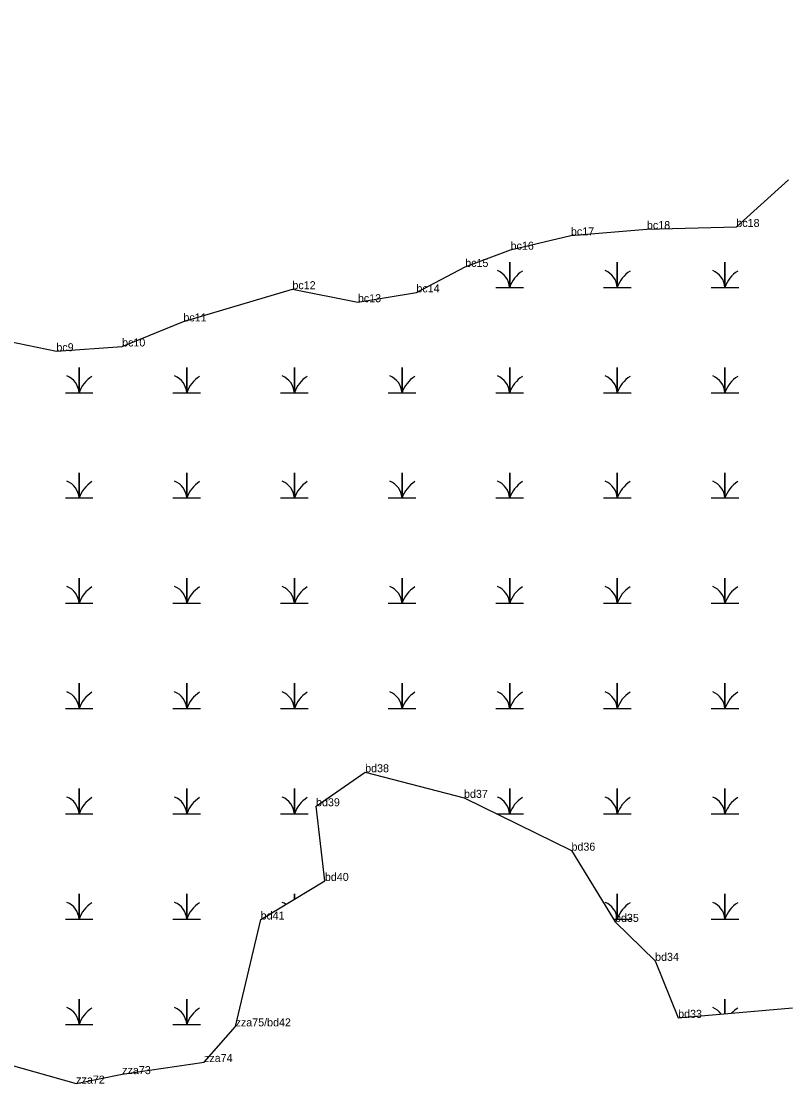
# Model space of a CAD drawing. Extents: x 2072529 to 2268796, y 436423 to 470406.
# Drawn here: x 2214824 to 2215304, y 439449 to 440113 of the extents above; entities that cross this region are included whole.
import ezdxf

# ---------------------------------------------------------------- set-up
doc = ezdxf.new("R2010")
doc.units = 0
for name, color, linetype in [('Exist Environmental Wetland Boundary', 7, 'Continuous'), ('Exist Environmental Wetland Boundary Cogo Comment', 7, 'Continuous'), ('Exist Hydro Swamp or Marsh', 7, 'Continuous'), ('Old_Level_20', 7, 'Continuous')]:
    doc.layers.add(name, color=color, linetype=linetype)

msp = doc.modelspace()

# ---------------------------------------------------------------- linework, layer by layer
at = {"layer": 'Exist Environmental Wetland Boundary'}
for points in [[(2214667.01, 440113.14), (2214653.54, 440085.32), (2214640.79, 440044.09), (2214670.86, 440006.51), (2214705.05, 439986.15), (2214750.6, 439980.47), (2214768.48, 439956.79), (2214803.77, 439915.77), (2214846.21, 439906.91), (2214887.26, 439909.88), (2214925.55, 439925.54), (2214993.67, 439945.68), (2215034.57, 439937.55), (2215071.14, 439943.7), (2215101.61, 439959.58), (2215129.98, 439970.34), (2215167.67, 439979.26), (2215215.16, 439983.25), (2215271.02, 439984.57), (2215303.54, 440013.99)], [(2214798.67, 439466.07), (2214858.58, 439449.17), (2214887.32, 439455.11), (2214938.43, 439462.67), (2214958.15, 439484.96), (2214973.84, 439551.74), (2215013.96, 439575.86), (2215008.43, 439622.52), (2215039.12, 439643.79), (2215100.88, 439627.77), (2215168.02, 439594.78), (2215195.22, 439550.26), (2215220.25, 439525.91), (2215234.65, 439490.29), (2215306.13, 439496.6)]]:
    msp.add_lwpolyline(points, dxfattribs=at)
at = {"layer": 'Exist Hydro Swamp or Marsh'}
for points in [[(2215120.8, 439946.79), (2215129.4, 439946.79), (2215129.4, 439962.57), (2215129.4, 439946.79), (2215138, 439946.79)], [(2215188.05, 439946.79), (2215196.65, 439946.79), (2215196.65, 439962.57), (2215196.65, 439946.79), (2215205.25, 439946.79)], [(2215255.3, 439946.79), (2215263.9, 439946.79), (2215263.9, 439962.57), (2215263.9, 439946.79), (2215272.5, 439946.79)], [(2214851.8, 439880.99), (2214860.4, 439880.99), (2214860.4, 439896.77), (2214860.4, 439880.99), (2214869, 439880.99)], [(2214919.05, 439880.99), (2214927.65, 439880.99), (2214927.65, 439896.77), (2214927.65, 439880.99), (2214936.25, 439880.99)], [(2214986.3, 439880.99), (2214994.9, 439880.99), (2214994.9, 439896.77), (2214994.9, 439880.99), (2215003.5, 439880.99)], [(2215053.55, 439880.99), (2215062.15, 439880.99), (2215062.15, 439896.77), (2215062.15, 439880.99), (2215070.75, 439880.99)], [(2215120.8, 439880.99), (2215129.4, 439880.99), (2215129.4, 439896.77), (2215129.4, 439880.99), (2215138, 439880.99)], [(2215188.05, 439880.99), (2215196.65, 439880.99), (2215196.65, 439896.77), (2215196.65, 439880.99), (2215205.25, 439880.99)], [(2215255.3, 439880.99), (2215263.9, 439880.99), (2215263.9, 439896.77), (2215263.9, 439880.99), (2215272.5, 439880.99)], [(2214851.8, 439815.19), (2214860.4, 439815.19), (2214860.4, 439830.97), (2214860.4, 439815.19), (2214869, 439815.19)], [(2214919.05, 439815.19), (2214927.65, 439815.19), (2214927.65, 439830.97), (2214927.65, 439815.19), (2214936.25, 439815.19)], [(2214986.3, 439815.19), (2214994.9, 439815.19), (2214994.9, 439830.97), (2214994.9, 439815.19), (2215003.5, 439815.19)], [(2215053.55, 439815.19), (2215062.15, 439815.19), (2215062.15, 439830.97), (2215062.15, 439815.19), (2215070.75, 439815.19)], [(2215120.8, 439815.19), (2215129.4, 439815.19), (2215129.4, 439830.97), (2215129.4, 439815.19), (2215138, 439815.19)], [(2215188.05, 439815.19), (2215196.65, 439815.19), (2215196.65, 439830.97), (2215196.65, 439815.19), (2215205.25, 439815.19)], [(2215255.3, 439815.19), (2215263.9, 439815.19), (2215263.9, 439830.97), (2215263.9, 439815.19), (2215272.5, 439815.19)], [(2214851.8, 439749.39), (2214860.4, 439749.39), (2214860.4, 439765.17), (2214860.4, 439749.39), (2214869, 439749.39)], [(2214919.05, 439749.39), (2214927.65, 439749.39), (2214927.65, 439765.17), (2214927.65, 439749.39), (2214936.25, 439749.39)], [(2214986.3, 439749.39), (2214994.9, 439749.39), (2214994.9, 439765.17), (2214994.9, 439749.39), (2215003.5, 439749.39)], [(2215053.55, 439749.39), (2215062.15, 439749.39), (2215062.15, 439765.17), (2215062.15, 439749.39), (2215070.75, 439749.39)], [(2215120.8, 439749.39), (2215129.4, 439749.39), (2215129.4, 439765.17), (2215129.4, 439749.39), (2215138, 439749.39)], [(2215188.05, 439749.39), (2215196.65, 439749.39), (2215196.65, 439765.17), (2215196.65, 439749.39), (2215205.25, 439749.39)], [(2215255.3, 439749.39), (2215263.9, 439749.39), (2215263.9, 439765.17), (2215263.9, 439749.39), (2215272.5, 439749.39)], [(2214851.8, 439683.59), (2214860.4, 439683.59), (2214860.4, 439699.37), (2214860.4, 439683.59), (2214869, 439683.59)], [(2214919.05, 439683.59), (2214927.65, 439683.59), (2214927.65, 439699.37), (2214927.65, 439683.59), (2214936.25, 439683.59)], [(2214986.3, 439683.59), (2214994.9, 439683.59), (2214994.9, 439699.37), (2214994.9, 439683.59), (2215003.5, 439683.59)], [(2215053.55, 439683.59), (2215062.15, 439683.59), (2215062.15, 439699.37), (2215062.15, 439683.59), (2215070.75, 439683.59)], [(2215120.8, 439683.59), (2215129.4, 439683.59), (2215129.4, 439699.37), (2215129.4, 439683.59), (2215138, 439683.59)], [(2215188.05, 439683.59), (2215196.65, 439683.59), (2215196.65, 439699.37), (2215196.65, 439683.59), (2215205.25, 439683.59)], [(2215255.3, 439683.59), (2215263.9, 439683.59), (2215263.9, 439699.37), (2215263.9, 439683.59), (2215272.5, 439683.59)], [(2214851.8, 439617.79), (2214860.4, 439617.79), (2214860.4, 439633.57), (2214860.4, 439617.79), (2214869, 439617.79)], [(2214919.05, 439617.79), (2214927.65, 439617.79), (2214927.65, 439633.57), (2214927.65, 439617.79), (2214936.25, 439617.79)], [(2214986.3, 439617.79), (2214994.9, 439617.79), (2214994.9, 439633.57), (2214994.9, 439617.79), (2215003.5, 439617.79)], [(2215121.2, 439617.79), (2215129.4, 439617.79), (2215129.4, 439633.57), (2215129.4, 439617.79), (2215138, 439617.79)], [(2215188.05, 439617.79), (2215196.65, 439617.79), (2215196.65, 439633.57), (2215196.65, 439617.79), (2215205.25, 439617.79)], [(2215255.3, 439617.79), (2215263.9, 439617.79), (2215263.9, 439633.57), (2215263.9, 439617.79), (2215272.5, 439617.79)], [(2214851.8, 439551.99), (2214860.4, 439551.99), (2214860.4, 439567.77), (2214860.4, 439551.99), (2214869, 439551.99)], [(2214919.05, 439551.99), (2214927.65, 439551.99), (2214927.65, 439567.77), (2214927.65, 439551.99), (2214936.25, 439551.99)], [(2214994.9, 439564.4), (2214994.9, 439567.77), (2214994.9, 439564.4)], [(2215194.17, 439551.99), (2215196.65, 439551.99), (2215196.65, 439567.77), (2215196.65, 439551.99), (2215205.25, 439551.99)], [(2215255.3, 439551.99), (2215263.9, 439551.99), (2215263.9, 439567.77), (2215263.9, 439551.99), (2215272.5, 439551.99)], [(2214851.8, 439486.19), (2214860.4, 439486.19), (2214860.4, 439501.97), (2214860.4, 439486.19), (2214869, 439486.19)], [(2214919.05, 439486.19), (2214927.65, 439486.19), (2214927.65, 439501.97), (2214927.65, 439486.19), (2214936.25, 439486.19)], [(2215263.9, 439492.87), (2215263.9, 439501.97), (2215263.9, 439492.87)]]:
    msp.add_lwpolyline(points, dxfattribs=at)
for centre, radius, start, end in [((2215117.13, 439945.9), 12.3, 4.14034, 67.53497), ((2215147.64, 439940.72), 19.22, 122.12745, 161.62219), ((2215184.38, 439945.9), 12.3, 4.14034, 67.53497), ((2215214.89, 439940.72), 19.22, 122.12745, 161.62219), ((2215251.63, 439945.9), 12.3, 4.14034, 67.53497), ((2215282.14, 439940.72), 19.22, 122.12745, 161.62219), ((2214848.13, 439880.1), 12.3, 4.14034, 67.53497), ((2214878.64, 439874.92), 19.22, 122.12745, 161.62219), ((2214915.38, 439880.1), 12.3, 4.14034, 67.53497), ((2214945.89, 439874.92), 19.22, 122.12745, 161.62219), ((2214982.63, 439880.1), 12.3, 4.14034, 67.53497), ((2215013.14, 439874.92), 19.22, 122.12745, 161.62219), ((2215049.88, 439880.1), 12.3, 4.14034, 67.53497), ((2215080.39, 439874.92), 19.22, 122.12745, 161.62219), ((2215117.13, 439880.1), 12.3, 4.14034, 67.53497), ((2215147.64, 439874.92), 19.22, 122.12745, 161.62219), ((2215184.38, 439880.1), 12.3, 4.14034, 67.53497), ((2215214.89, 439874.92), 19.22, 122.12745, 161.62219), ((2215251.63, 439880.1), 12.3, 4.14034, 67.53497), ((2215282.14, 439874.92), 19.22, 122.12745, 161.62219), ((2214848.13, 439814.3), 12.3, 4.14034, 67.53497), ((2214878.64, 439809.12), 19.22, 122.12745, 161.62219), ((2214915.38, 439814.3), 12.3, 4.14034, 67.53497), ((2214945.89, 439809.12), 19.22, 122.12745, 161.62219), ((2214982.63, 439814.3), 12.3, 4.14034, 67.53497), ((2215013.14, 439809.12), 19.22, 122.12745, 161.62219), ((2215049.88, 439814.3), 12.3, 4.14034, 67.53497), ((2215080.39, 439809.12), 19.22, 122.12745, 161.62219), ((2215117.13, 439814.3), 12.3, 4.14034, 67.53497), ((2215147.64, 439809.12), 19.22, 122.12745, 161.62219), ((2215184.38, 439814.3), 12.3, 4.14034, 67.53497), ((2215214.89, 439809.12), 19.22, 122.12745, 161.62219), ((2215251.63, 439814.3), 12.3, 4.14034, 67.53497), ((2215282.14, 439809.12), 19.22, 122.12745, 161.62219), ((2214848.13, 439748.5), 12.3, 4.14034, 67.53497), ((2214878.64, 439743.32), 19.22, 122.12745, 161.62219), ((2214915.38, 439748.5), 12.3, 4.14034, 67.53497), ((2214945.89, 439743.32), 19.22, 122.12745, 161.62219), ((2214982.63, 439748.5), 12.3, 4.14034, 67.53497), ((2215013.14, 439743.32), 19.22, 122.12745, 161.62219), ((2215049.88, 439748.5), 12.3, 4.14034, 67.53497), ((2215080.39, 439743.32), 19.22, 122.12745, 161.62219), ((2215117.13, 439748.5), 12.3, 4.14034, 67.53497), ((2215147.64, 439743.32), 19.22, 122.12745, 161.62219), ((2215184.38, 439748.5), 12.3, 4.14034, 67.53497), ((2215214.89, 439743.32), 19.22, 122.12745, 161.62219), ((2215251.63, 439748.5), 12.3, 4.14034, 67.53497), ((2215282.14, 439743.32), 19.22, 122.12745, 161.62219), ((2214848.13, 439682.7), 12.3, 4.14034, 67.53497), ((2214878.64, 439677.52), 19.22, 122.12745, 161.62219), ((2214915.38, 439682.7), 12.3, 4.14034, 67.53497), ((2214945.89, 439677.52), 19.22, 122.12745, 161.62219), ((2214982.63, 439682.7), 12.3, 4.14034, 67.53497), ((2215013.14, 439677.52), 19.22, 122.12745, 161.62219), ((2215049.88, 439682.7), 12.3, 4.14034, 67.53497), ((2215080.39, 439677.52), 19.22, 122.12745, 161.62219), ((2215117.13, 439682.7), 12.3, 4.14034, 67.53497), ((2215147.64, 439677.52), 19.22, 122.12745, 161.62219), ((2215184.38, 439682.7), 12.3, 4.14034, 67.53497), ((2215214.89, 439677.52), 19.22, 122.12745, 161.62219), ((2215251.63, 439682.7), 12.3, 4.14034, 67.53497), ((2215282.14, 439677.52), 19.22, 122.12745, 161.62219), ((2214848.13, 439616.9), 12.3, 4.14034, 67.53497), ((2214878.64, 439611.72), 19.22, 122.12745, 161.62219), ((2214915.38, 439616.9), 12.3, 4.14034, 67.53497), ((2214945.89, 439611.72), 19.22, 122.12745, 161.62219), ((2214982.63, 439616.9), 12.3, 4.14034, 67.53497), ((2215013.14, 439611.72), 19.22, 122.12745, 161.62219), ((2215117.13, 439616.9), 12.3, 4.14034, 67.53497), ((2215147.64, 439611.72), 19.22, 122.12745, 161.62219), ((2215184.38, 439616.9), 12.3, 4.14034, 67.53497), ((2215214.89, 439611.72), 19.22, 122.12745, 161.62219), ((2215251.63, 439616.9), 12.3, 4.14034, 67.53497), ((2215282.14, 439611.72), 19.22, 122.12745, 161.62219), ((2214848.13, 439551.1), 12.3, 4.14034, 67.53497), ((2214878.64, 439545.92), 19.22, 122.12745, 161.62219), ((2214915.38, 439551.1), 12.3, 4.14034, 67.53497), ((2214945.89, 439545.92), 19.22, 122.12745, 161.62219), ((2214982.63, 439551.1), 12.3, 55.41579, 67.53497), ((2215184.38, 439551.1), 12.3, 4.14034, 67.53497), ((2215214.89, 439545.92), 19.22, 122.12745, 161.62219), ((2215251.63, 439551.1), 12.3, 4.14034, 67.53497), ((2215282.14, 439545.92), 19.22, 122.12745, 161.62219), ((2214848.13, 439485.3), 12.3, 4.14034, 67.53497), ((2214878.64, 439480.12), 19.22, 122.12745, 161.62219), ((2214915.38, 439485.3), 12.3, 4.14034, 67.53497), ((2214945.89, 439480.12), 19.22, 122.12745, 161.62219), ((2215251.63, 439485.3), 12.3, 36.75102, 67.53497), ((2215282.14, 439480.12), 19.22, 122.12745, 136.98485)]:
    msp.add_arc(centre, radius, start, end, dxfattribs=at)
at = {"layer": 'Old_Level_20'}
for p, q in [((2215303.54, 440013.99), (2215303.54, 440013.99)), ((2215215.16, 439983.25), (2215215.16, 439983.25)), ((2215271.02, 439984.57), (2215271.02, 439984.57)), ((2215167.67, 439979.26), (2215167.67, 439979.26)), ((2215129.98, 439970.34), (2215129.98, 439970.34)), ((2215101.61, 439959.58), (2215101.61, 439959.58)), ((2214993.67, 439945.68), (2214993.67, 439945.68)), ((2215071.14, 439943.7), (2215071.14, 439943.7)), ((2215034.57, 439937.55), (2215034.57, 439937.55)), ((2214925.55, 439925.54), (2214925.55, 439925.54)), ((2214887.26, 439909.88), (2214887.26, 439909.88)), ((2214846.21, 439906.91), (2214846.21, 439906.91)), ((2215039.12, 439643.79), (2215039.12, 439643.79)), ((2215100.88, 439627.77), (2215100.88, 439627.77)), ((2215008.43, 439622.52), (2215008.43, 439622.52)), ((2215168.02, 439594.78), (2215168.02, 439594.78)), ((2215013.96, 439575.86), (2215013.96, 439575.86)), ((2214973.84, 439551.74), (2214973.84, 439551.74)), ((2215195.22, 439550.26), (2215195.22, 439550.26)), ((2215220.25, 439525.91), (2215220.25, 439525.91)), ((2214958.15, 439484.96), (2214958.15, 439484.96)), ((2215234.65, 439490.29), (2215234.65, 439490.29)), ((2214938.43, 439462.67), (2214938.43, 439462.67)), ((2214887.32, 439455.11), (2214887.32, 439455.11)), ((2214858.58, 439449.17), (2214858.58, 439449.17))]:
    msp.add_line(p, q, dxfattribs=at)

# ---------------------------------------------------------------- texts
at = {"layer": 'Exist Environmental Wetland Boundary Cogo Comment'}
for s, p in [('bc18', (2215271.02, 439984.57)), ('bc17', (2215167.67, 439979.26)), ('bc18', (2215215.16, 439983.25)), ('bc16', (2215129.98, 439970.34)), ('bc15', (2215101.61, 439959.58)), ('bc12', (2214993.67, 439945.68)), ('bc14', (2215071.14, 439943.7)), ('bc13', (2215034.57, 439937.55)), ('bc11', (2214925.55, 439925.54)), ('bc9', (2214846.21, 439906.91)), ('bc10', (2214887.26, 439909.88)), ('bd38', (2215039.12, 439643.79)), ('bd37', (2215100.88, 439627.77)), ('bd39', (2215008.43, 439622.52)), ('bd36', (2215168.02, 439594.78)), ('bd40', (2215013.96, 439575.86)), ('bd41', (2214973.84, 439551.74)), ('bd35', (2215195.22, 439550.26)), ('bd34', (2215220.25, 439525.91)), ('bd33', (2215234.65, 439490.29)), ('zza75/bd42', (2214958.15, 439484.96)), ('zza74', (2214938.43, 439462.67)), ('zza73', (2214887.32, 439455.11)), ('zza72', (2214858.58, 439449.17))]:
    msp.add_text(s, height=5, dxfattribs=at).set_placement(p)

doc.saveas('drawing.dxf')
